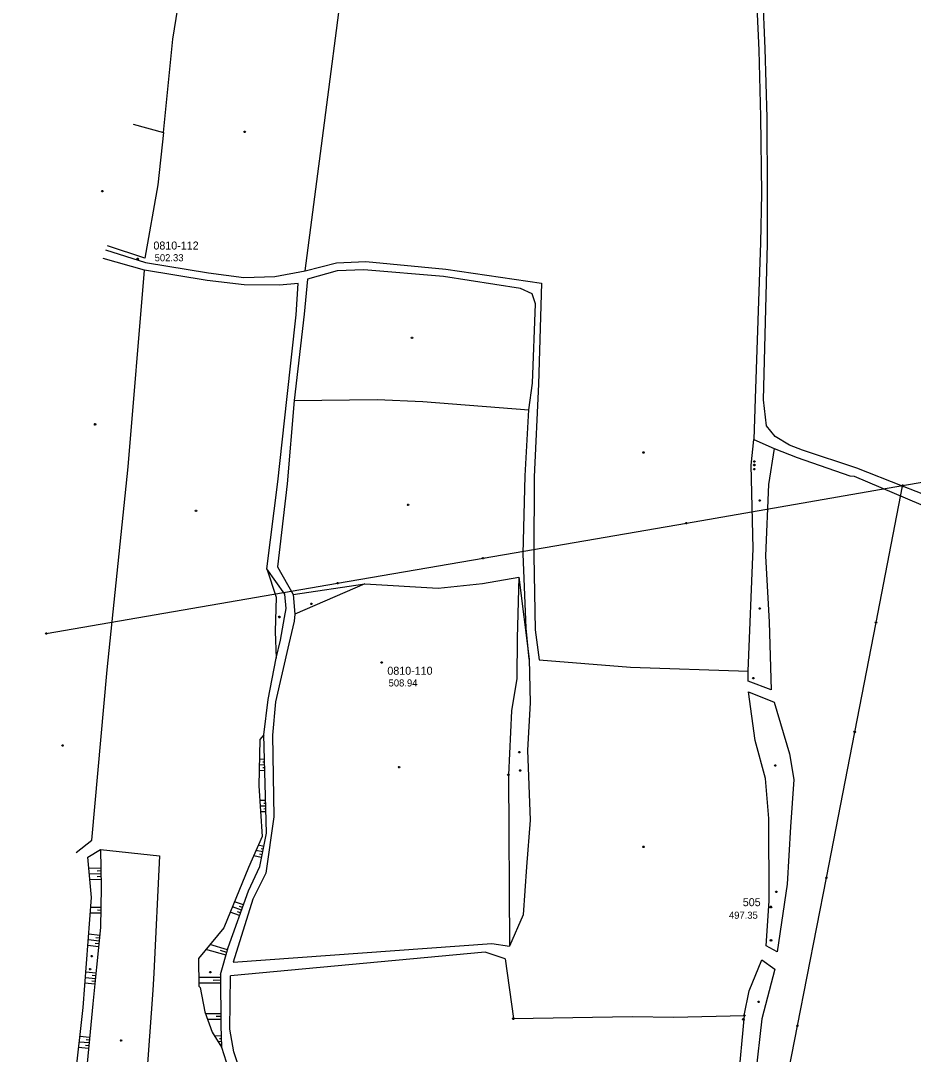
# Model space of a CAD drawing. Extents: x -664960 to -662754, y -993849 to -991145.
# Drawn here: x -664861.7 to -664482.4, y -993104.4 to -992665.4 of the extents above; entities that cross this region are included whole.
import ezdxf

# ---------------------------------------------------------------- set-up
doc = ezdxf.new("R2010")
doc.units = 0
for name, color, linetype in [('Vrstva 1', 7, 'Continuous'), ('Vrstva 12', 7, 'Continuous'), ('Vrstva 13', 7, 'Continuous'), ('Vrstva 18', 7, 'Continuous'), ('Vrstva 27', 7, 'Continuous'), ('Vrstva 29', 7, 'Continuous'), ('Vrstva 37', 7, 'Continuous'), ('Vrstva 57', 7, 'Continuous'), ('Vrstva 63', 7, 'Continuous'), ('Vrstva 8', 7, 'Continuous')]:
    doc.layers.add(name, color=color, linetype=linetype)

msp = doc.modelspace()

# ---------------------------------------------------------------- linework, layer by layer
at = {"layer": 'Vrstva 12'}
msp.add_lwpolyline([(-664813.951, -992709.374), (-664800.96, -992712.82), (-664803.48, -992735.03), (-664809.02, -992766.19), (-664824.81, -992761.06)], dxfattribs=at)
at = {"layer": 'Vrstva 13'}
for points in [[(-664766.347, -992712.286), (-664766.167, -992712.586), (-664766.347, -992712.886), (-664766.707, -992712.886), (-664766.887, -992712.586), (-664766.707, -992712.286), (-664766.347, -992712.286)], [(-664826.854, -992737.453), (-664826.674, -992737.753), (-664826.854, -992738.053), (-664827.214, -992738.053), (-664827.394, -992737.753), (-664827.214, -992737.453), (-664826.854, -992737.453)], [(-664695.26, -992799.766), (-664695.08, -992800.066), (-664695.26, -992800.366), (-664695.62, -992800.366), (-664695.8, -992800.066), (-664695.62, -992799.766), (-664695.26, -992799.766)], [(-664829.885, -992836.502), (-664829.705, -992836.802), (-664829.885, -992837.102), (-664830.245, -992837.102), (-664830.425, -992836.802), (-664830.245, -992836.502), (-664829.885, -992836.502)], [(-664596.895, -992848.458), (-664596.715, -992848.758), (-664596.895, -992849.058), (-664597.255, -992849.058), (-664597.435, -992848.758), (-664597.255, -992848.458), (-664596.895, -992848.458)], [(-664696.913, -992870.741), (-664696.733, -992871.041), (-664696.913, -992871.341), (-664697.273, -992871.341), (-664697.453, -992871.041), (-664697.273, -992870.741), (-664696.913, -992870.741)], [(-664547.497, -992868.823), (-664547.317, -992869.123), (-664547.497, -992869.423), (-664547.857, -992869.423), (-664548.037, -992869.123), (-664547.857, -992868.823), (-664547.497, -992868.823)], [(-664787.011, -992873.217), (-664786.831, -992873.517), (-664787.011, -992873.817), (-664787.371, -992873.817), (-664787.551, -992873.517), (-664787.371, -992873.217), (-664787.011, -992873.217)], [(-664737.988, -992912.78), (-664737.808, -992913.08), (-664737.988, -992913.38), (-664738.348, -992913.38), (-664738.528, -992913.08), (-664738.348, -992912.78), (-664737.988, -992912.78)], [(-664547.497, -992914.751), (-664547.317, -992915.051), (-664547.497, -992915.351), (-664547.857, -992915.351), (-664548.037, -992915.051), (-664547.857, -992914.751), (-664547.497, -992914.751)], [(-664751.581, -992918.346), (-664751.401, -992918.646), (-664751.581, -992918.946), (-664751.941, -992918.946), (-664752.121, -992918.646), (-664751.941, -992918.346), (-664751.581, -992918.346)], [(-664843.741, -992972.897), (-664843.561, -992973.197), (-664843.741, -992973.497), (-664844.101, -992973.497), (-664844.281, -992973.197), (-664844.101, -992972.897), (-664843.741, -992972.897)], [(-664649.659, -992975.744), (-664649.479, -992976.044), (-664649.659, -992976.344), (-664650.019, -992976.344), (-664650.199, -992976.044), (-664650.019, -992975.744), (-664649.659, -992975.744)], [(-664700.722, -992982.14), (-664700.542, -992982.44), (-664700.722, -992982.74), (-664701.082, -992982.74), (-664701.262, -992982.44), (-664701.082, -992982.14), (-664700.722, -992982.14)], [(-664540.942, -992981.379), (-664540.762, -992981.679), (-664540.942, -992981.979), (-664541.302, -992981.979), (-664541.482, -992981.679), (-664541.302, -992981.379), (-664540.942, -992981.379)], [(-664649.298, -992983.518), (-664649.118, -992983.818), (-664649.298, -992984.118), (-664649.658, -992984.118), (-664649.838, -992983.818), (-664649.658, -992983.518), (-664649.298, -992983.518)], [(-664596.895, -993015.992), (-664596.715, -993016.292), (-664596.895, -993016.592), (-664597.255, -993016.592), (-664597.435, -993016.292), (-664597.255, -993015.992), (-664596.895, -993015.992)], [(-664540.424, -993035.07), (-664540.244, -993035.37), (-664540.424, -993035.67), (-664540.784, -993035.67), (-664540.964, -993035.37), (-664540.784, -993035.07), (-664540.424, -993035.07)], [(-664831.3, -993062.334), (-664831.12, -993062.634), (-664831.3, -993062.934), (-664831.66, -993062.934), (-664831.84, -993062.634), (-664831.66, -993062.334), (-664831.3, -993062.334)], [(-664832.016, -993067.929), (-664831.836, -993068.229), (-664832.016, -993068.529), (-664832.376, -993068.529), (-664832.556, -993068.229), (-664832.376, -993067.929), (-664832.016, -993067.929)], [(-664780.956, -993069.225), (-664780.776, -993069.525), (-664780.956, -993069.825), (-664781.316, -993069.825), (-664781.496, -993069.525), (-664781.316, -993069.225), (-664780.956, -993069.225)], [(-664548.014, -993081.807), (-664547.834, -993082.107), (-664548.014, -993082.407), (-664548.374, -993082.407), (-664548.554, -993082.107), (-664548.374, -993081.807), (-664548.014, -993081.807)], [(-664818.837, -993098.191), (-664818.657, -993098.491), (-664818.837, -993098.791), (-664819.197, -993098.791), (-664819.377, -993098.491), (-664819.197, -993098.191), (-664818.837, -993098.191)]]:
    msp.add_lwpolyline(points, dxfattribs=at)
at = {"layer": 'Vrstva 18'}
for points in [[(-664654.29, -992985.33), (-664654.11, -992985.63), (-664654.29, -992985.93), (-664654.65, -992985.93), (-664654.83, -992985.63), (-664654.65, -992985.33), (-664654.29, -992985.33)], [(-664554.07, -993087.64), (-664553.89, -993087.94), (-664554.07, -993088.24), (-664554.43, -993088.24), (-664554.61, -993087.94), (-664554.43, -993087.64), (-664554.07, -993087.64)], [(-664652.17, -993088.92), (-664651.99, -993089.22), (-664652.17, -993089.52), (-664652.53, -993089.52), (-664652.71, -993089.22), (-664652.53, -993088.92), (-664652.17, -993088.92)]]:
    msp.add_lwpolyline(points, dxfattribs=at)
at = {"layer": 'Vrstva 27'}
for points in [[(-664549.26, -992653.21), (-664548.03, -992677.85), (-664547.4, -992706.27), (-664546.88, -992738.77), (-664547.41, -992759.68), (-664549.63, -992825.84), (-664550.21, -992843.18), (-664541.56, -992847.02), (-664531.738, -992850.961), (-664509.431, -992858.668), (-664507.541, -992858.79), (-664467.903, -992875.621), (-664436.08, -992888.029), (-664408.092, -992896.554), (-664386.885, -992895.077), (-664374.052, -992898.604), (-664348.318, -992906.034), (-664324.204, -992913.897), (-664309.56, -992921.692), (-664284.985, -992937.084), (-664263.986, -992955.329), (-664251.663, -992973.809), (-664241.683, -992988.903), (-664240.873, -992991.914)], [(-664463.793, -992872.084), (-664487.02, -992863.072), (-664506.398, -992855.488), (-664529.544, -992847.783), (-664535, -992845.62), (-664541.14, -992842.02), (-664544.77, -992837.4), (-664546.1, -992826.44), (-664544.46, -992760.18), (-664544.35, -992738.4), (-664544.54, -992706.6), (-664545.38, -992677.24), (-664546.38, -992653.52)], [(-664825.73, -992762.66), (-664808.65, -992768.08), (-664781.85, -992772.4), (-664766.92, -992774.42), (-664753.75, -992773.95), (-664740.88, -992771.61), (-664727.55, -992768.23), (-664715.01, -992767.59), (-664681.1, -992770.9), (-664640.46, -992776.78), (-664641.66, -992819.75), (-664643.57, -992859.11), (-664643.74, -992892.6), (-664643.11, -992924.06), (-664641.42, -992936.82)], [(-664776.82, -993070.5), (-664773.54, -993059.03), (-664764.9, -993034.95), (-664760.12, -993024.65), (-664757.31, -993010.47), (-664758.33, -992968.66), (-664756.58, -992953.66), (-664753.09, -992936.06), (-664751.24, -992928.44), (-664749.63, -992918.9), (-664748.95, -992914.99), (-664749.52, -992909), (-664757.07, -992898.13), (-664752.39, -992861.25), (-664748.63, -992826.29), (-664744.62, -992790.3), (-664743.77, -992777.04), (-664751.77, -992777.72), (-664766.79, -992777.55), (-664782.49, -992775.73), (-664809.14, -992771.38), (-664826.69, -992766.35)], [(-664645.72, -992936.59), (-664646.98, -992923.41), (-664648.14, -992891.87), (-664647.42, -992858.62), (-664645.74, -992830.7), (-664644.28, -992819.27), (-664643.03, -992785.66), (-664644.35, -992781.31), (-664649.31, -992779.12), (-664682.11, -992773.97), (-664715.92, -992771.21), (-664727.27, -992771.63), (-664739.9, -992775.12), (-664741.19, -992790.04), (-664745.55, -992826.68), (-664748.49, -992862.04), (-664752.56, -992897.35), (-664745.96, -992909.01), (-664745.22, -992917.44), (-664745.54, -992920.45), (-664747.76, -992930.07), (-664753.45, -992954.63), (-664754.76, -992968.76), (-664754.08, -993003.44), (-664757.51, -993027.48), (-664763.09, -993038.52), (-664771.44, -993065.28), (-664661.57, -993057.32), (-664653.95, -993058.39)], [(-664655.82, -993063.79), (-664664.37, -993061.05), (-664772.56, -993071.1)], [(-664776.82, -993070.5), (-664776.67, -993092.1), (-664776.38, -993101.37), (-664771.43, -993116.89)], [(-664758.94, -993139.61), (-664771.07, -993103.34), (-664772.77, -993093.75), (-664772.56, -993071.1)]]:
    msp.add_lwpolyline(points, dxfattribs=at)
at = {"layer": 'Vrstva 29'}
msp.add_lwpolyline([(-664549.8, -992853.79), (-664549.62, -992854.09), (-664549.8, -992854.39), (-664550.16, -992854.39), (-664550.34, -992854.09), (-664550.16, -992853.79), (-664549.8, -992853.79)], dxfattribs=at)
at = {"layer": 'Vrstva 37'}
for points in [[(-664486.84, -992862.772), (-664486.66, -992863.072), (-664486.84, -992863.372), (-664487.2, -992863.372), (-664487.38, -992863.072), (-664487.2, -992862.772), (-664486.84, -992862.772)], [(-664486.795, -992862.482), (-664486.615, -992862.782), (-664486.795, -992863.082), (-664487.155, -992863.082), (-664487.335, -992862.782), (-664487.155, -992862.482), (-664486.795, -992862.482)], [(-664578.69, -992878.53), (-664578.51, -992878.83), (-664578.69, -992879.13), (-664579.05, -992879.13), (-664579.23, -992878.83), (-664579.05, -992878.53), (-664578.69, -992878.53)], [(-664665.09, -992893.36), (-664664.91, -992893.66), (-664665.09, -992893.96), (-664665.45, -992893.96), (-664665.63, -992893.66), (-664665.45, -992893.36), (-664665.09, -992893.36)], [(-664726.89, -992903.97), (-664726.71, -992904.27), (-664726.89, -992904.57), (-664727.25, -992904.57), (-664727.43, -992904.27), (-664727.25, -992903.97), (-664726.89, -992903.97)], [(-664498.111, -992920.62), (-664497.931, -992920.92), (-664498.111, -992921.22), (-664498.471, -992921.22), (-664498.651, -992920.92), (-664498.471, -992920.62), (-664498.111, -992920.62)], [(-664850.67, -992925.29), (-664850.49, -992925.59), (-664850.67, -992925.89), (-664851.03, -992925.89), (-664851.21, -992925.59), (-664851.03, -992925.29), (-664850.67, -992925.29)], [(-664507.134, -992967.179), (-664506.954, -992967.479), (-664507.134, -992967.779), (-664507.494, -992967.779), (-664507.674, -992967.479), (-664507.494, -992967.179), (-664507.134, -992967.179)], [(-664519.153, -993029.127), (-664518.973, -993029.427), (-664519.153, -993029.727), (-664519.513, -993029.727), (-664519.693, -993029.427), (-664519.513, -993029.127), (-664519.153, -993029.127)], [(-664531.485, -993092.029), (-664531.305, -993092.329), (-664531.485, -993092.629), (-664531.845, -993092.629), (-664532.025, -993092.329), (-664531.845, -993092.029), (-664531.485, -993092.029)]]:
    msp.add_lwpolyline(points, dxfattribs=at)
at = {"layer": 'Vrstva 57'}
for points in [[(-664850.85, -992925.59), (-664727.07, -992904.27), (-664665.27, -992893.66), (-664578.87, -992878.83), (-664486.975, -992862.782), (-664378.158, -992844.317), (-664294.99, -992830.081), (-664180.69, -992810.49)], [(-664522.999, -993424.664), (-664549.676, -993372.01), (-664575.68, -993321.894), (-664564.945, -993264.353), (-664554.433, -993209.057), (-664543.48, -993153.084), (-664531.665, -993092.329), (-664519.333, -993029.427), (-664507.314, -992967.479), (-664498.291, -992920.92), (-664487.02, -992863.072)]]:
    msp.add_lwpolyline(points, dxfattribs=at)
at = {"layer": 'Vrstva 63'}
for p, q in [((-664758.017, -992981.483), (-664760.287, -992981.538)), ((-664758.076, -992979.083), (-664760.237, -992979.136)), ((-664758.046, -992980.283), (-664758.784, -992980.301)), ((-664757.959, -992983.882), (-664760.337, -992983.94)), ((-664757.988, -992982.682), (-664758.762, -992982.701)), ((-664757.649, -992996.579), (-664760.081, -992996.638)), ((-664757.59, -992998.978), (-664759.933, -992999.035)), ((-664757.62, -992997.778), (-664758.415, -992997.798)), ((-664757.532, -993001.377), (-664759.785, -993001.432)), ((-664757.561, -993000.178), (-664758.326, -993000.196)), ((-664758.418, -993016.06), (-664760.762, -993015.596)), ((-664758.651, -993017.237), (-664759.519, -993017.065)), ((-664759.351, -993020.769), (-664762.738, -993020.097)), ((-664758.884, -993018.414), (-664761.75, -993017.846)), ((-664759.118, -993019.592), (-664760.159, -993019.385)), ((-664827.647, -993025.305), (-664832.677, -993025.41)), ((-664827.597, -993027.705), (-664832.459, -993027.806)), ((-664827.547, -993030.104), (-664832.24, -993030.202)), ((-664827.622, -993026.505), (-664829.269, -993026.539)), ((-664827.572, -993028.904), (-664829.163, -993028.938)), ((-664827.627, -993042.045), (-664831.878, -993041.973)), ((-664827.647, -993043.244), (-664829.087, -993043.22)), ((-664767.856, -993043.188), (-664771.737, -993041.796)), ((-664767.045, -993040.929), (-664770.83, -993039.571)), ((-664768.261, -993044.318), (-664769.57, -993043.849)), ((-664767.451, -993042.059), (-664768.727, -993041.601)), ((-664827.667, -993044.444), (-664832.064, -993044.37)), ((-664768.667, -993045.447), (-664772.643, -993044.021)), ((-664828.359, -993056.272), (-664832.954, -993055.8)), ((-664828.114, -993053.885), (-664832.768, -993053.407)), ((-664828.236, -993055.079), (-664829.776, -993054.921)), ((-664828.604, -993058.66), (-664833.14, -993058.194)), ((-664828.482, -993057.466), (-664830.002, -993057.31)), ((-664774.459, -993062.244), (-664782.969, -993059.81)), ((-664773.799, -993059.936), (-664781.295, -993057.793)), ((-664774.129, -993061.09), (-664776.794, -993060.328)), ((-664829.744, -993069.856), (-664834.015, -993069.435)), ((-664830.216, -993074.633), (-664834.387, -993074.222)), ((-664829.98, -993072.245), (-664834.201, -993071.828)), ((-664830.098, -993073.439), (-664831.495, -993073.301)), ((-664829.862, -993071.051), (-664831.276, -993070.911)), ((-664776.811, -993071.743), (-664786.062, -993071.807)), ((-664776.795, -993074.143), (-664786.015, -993074.207)), ((-664776.803, -993072.943), (-664779.878, -993072.964)), ((-664776.704, -993087.162), (-664783.12, -993087.206)), ((-664776.688, -993089.562), (-664782.269, -993089.6)), ((-664776.696, -993088.362), (-664778.693, -993088.376)), ((-664776.53, -993096.572), (-664779.303, -993096.659)), ((-664832.624, -993099.562), (-664836.818, -993099.161)), ((-664832.396, -993097.172), (-664836.553, -993096.775)), ((-664832.738, -993100.756), (-664834.141, -993100.622)), ((-664832.51, -993098.367), (-664833.9, -993098.234)), ((-664776.455, -993098.971), (-664777.842, -993099.015)), ((-664776.493, -993097.772), (-664777.185, -993097.793)), ((-664776.418, -993100.171), (-664776.648, -993100.178)), ((-664832.852, -993101.951), (-664837.084, -993101.546)), ((-664776.38, -993101.37), (-664776.38, -993101.37))]:
    msp.add_line(p, q, dxfattribs=at)
for points in [[(-664800.96, -992712.82), (-664797.02, -992673.16), (-664790.26, -992630.94), (-664785.81, -992582.58), (-664786.07, -992548.06), (-664785.94, -992543.77), (-664786.47, -992521.58), (-664789.59, -992497.46), (-664794, -992477.1), (-664797.68, -992463.73), (-664797.77, -992460.54), (-664807.2, -992434.68), (-664814.81, -992413.16), (-664819.55, -992398.64), (-664824.21, -992400.64)], [(-664740.88, -992771.61), (-664732.98, -992711.95), (-664724.72, -992647.59), (-664721.69, -992617.04), (-664718.92, -992552.98), (-664719.06, -992531.76), (-664721.04, -992495.55), (-664723.27, -992472.75), (-664729.45, -992426.22)], [(-664838.06, -993018.65), (-664831.53, -993013.42), (-664824.97, -992941.06), (-664816.06, -992854.88), (-664809.14, -992771.38)], [(-664745.55, -992826.68), (-664710.21, -992826.3), (-664690.81, -992827.09), (-664645.74, -992830.7)], [(-664542.77, -992949.6), (-664552.54, -992945.82), (-664552.67, -992941.65), (-664550.47, -992889.58), (-664551.29, -992854.12), (-664550.21, -992843.18)], [(-664541.56, -992847.02), (-664543.99, -992862.33), (-664545.23, -992892.67), (-664543.68, -992920.85), (-664542.77, -992949.6)], [(-664549.77, -992852.24), (-664549.59, -992852.54), (-664549.77, -992852.84), (-664550.13, -992852.84), (-664550.31, -992852.54), (-664550.13, -992852.24), (-664549.77, -992852.24)], [(-664549.85, -992855.58), (-664549.67, -992855.88), (-664549.85, -992856.18), (-664550.21, -992856.18), (-664550.39, -992855.88), (-664550.21, -992855.58), (-664549.85, -992855.58)], [(-664757.07, -992898.13), (-664753.11, -992910.21), (-664753.63, -992924.8), (-664753.09, -992936.06)], [(-664715.42, -992904.6), (-664684.31, -992906.39), (-664665.51, -992904.45), (-664650.04, -992901.74), (-664650.82, -992927.69), (-664650.85, -992944.79), (-664653.1, -992958.51), (-664654.47, -992985.63), (-664653.95, -993058.39)], [(-664650.04, -992901.74), (-664645.72, -992936.59), (-664645.21, -992955.05), (-664646.38, -992975.26), (-664645.28, -993004.89), (-664646.79, -993024.78), (-664648.2, -993045.12), (-664653.95, -993058.39)], [(-664745.96, -992909.01), (-664715.42, -992904.6), (-664745.22, -992917.44)], [(-664641.42, -992936.82), (-664602.54, -992939.99), (-664552.67, -992941.65)], [(-664550.23, -992944.29), (-664550.05, -992944.59), (-664550.23, -992944.89), (-664550.59, -992944.89), (-664550.77, -992944.59), (-664550.59, -992944.29), (-664550.23, -992944.29)], [(-664540.28, -993060.91), (-664544.96, -993058.26), (-664543.66, -993039.18), (-664543.76, -993004.16), (-664545.22, -992987.28), (-664549.58, -992971.06), (-664552.52, -992950.44), (-664541.49, -992954.8), (-664535.002, -992976.758), (-664533.139, -992987.638), (-664534.675, -993007.788), (-664536.025, -993032.07), (-664540.28, -993060.91)], [(-664758.33, -992968.66), (-664760.06, -992970.67), (-664760.47, -992990.32), (-664759.14, -993011.9), (-664764.93, -993025.09), (-664775.32, -993050.59), (-664786.22, -993063.73), (-664785.99, -993075.48), (-664785.5, -993076), (-664783.41, -993086.39), (-664780.37, -993094.94), (-664776.38, -993101.37)], [(-664831.55, -993037.76), (-664833.11, -993020.67), (-664827.81, -993017.45), (-664827.48, -993033.32), (-664827.77, -993050.54), (-664829.5, -993067.38), (-664831.04, -993082.99), (-664834.29, -993116.99), (-664836.8, -993137.97), (-664836.67, -993153.36), (-664835.64, -993165.38), (-664834.4, -993175.41), (-664846.97, -993182.62), (-664855.3, -993197.64), (-664859.62, -993209.7), (-664861.71, -993206.41), (-664858.51, -993197.12), (-664853.19, -993181.68), (-664846.56, -993165.7), (-664843.22, -993150.84), (-664841.14, -993136.53), (-664838.57, -993114.89), (-664835.19, -993084.54), (-664831.55, -993037.76)], [(-664827.81, -993017.45), (-664802.73, -993020.1), (-664805.16, -993069.86), (-664805.5, -993077.19), (-664811.42, -993157.27), (-664833.14, -993178.18), (-664834.4, -993175.41)], [(-664542.76, -993055.65), (-664542.58, -993055.95), (-664542.76, -993056.25), (-664543.12, -993056.25), (-664543.3, -993055.95), (-664543.12, -993055.65), (-664542.76, -993055.65)], [(-664655.82, -993063.79), (-664652.35, -993089.22), (-664601.96, -993088.33), (-664584.23, -993088.63), (-664554.25, -993087.94)], [(-664554.25, -993087.94), (-664552.21, -993077.47), (-664546.85, -993064.24), (-664541.29, -993068.2)], [(-664541.29, -993068.2), (-664546.848, -993089.32), (-664549.459, -993113.136), (-664550.45, -993153.095), (-664548.592, -993189.058), (-664550.275, -993205.084), (-664554.048, -993218.194), (-664563.831, -993237.797), (-664570.304, -993250.681), (-664566.308, -993263.028), (-664575.608, -993269.908), (-664575.58, -993270.94), (-664583.879, -993275.133)], [(-664554.25, -993087.94), (-664556.941, -993116.782), (-664555.472, -993152.376), (-664555.433, -993166.316), (-664555.866, -993180.523), (-664562.815, -993208.847), (-664567.677, -993230.44), (-664570.498, -993241.142), (-664581.807, -993246.578), (-664586.352, -993248.126), (-664607.195, -993246.026), (-664651.264, -993240.564), (-664666.443, -993238.925), (-664677.101, -993237.259), (-664696.743, -993250.798), (-664713.926, -993249.625), (-664732.687, -993253.923), (-664743.665, -993255.481), (-664754.532, -993256.093), (-664772.207, -993254.41)], [(-664554.51, -993089.21), (-664554.33, -993089.51), (-664554.51, -993089.81), (-664554.87, -993089.81), (-664555.05, -993089.51), (-664554.87, -993089.21), (-664554.51, -993089.21)]]:
    msp.add_lwpolyline(points, dxfattribs=at)
at = {"layer": 'Vrstva 8'}
for points in [[(-664811.82, -992766.27), (-664811.64, -992766.57), (-664811.82, -992766.87), (-664812.18, -992766.87), (-664812.36, -992766.57), (-664812.18, -992766.27), (-664811.82, -992766.27)], [(-664708.13, -992937.66), (-664707.95, -992937.96), (-664708.13, -992938.26), (-664708.49, -992938.26), (-664708.67, -992937.96), (-664708.49, -992937.66), (-664708.13, -992937.66)], [(-664542.8, -993041.49), (-664542.62, -993041.79), (-664542.8, -993042.09), (-664543.16, -993042.09), (-664543.34, -993041.79), (-664543.16, -993041.49), (-664542.8, -993041.49)]]:
    msp.add_lwpolyline(points, dxfattribs=at)

# ---------------------------------------------------------------- texts
at = {"layer": 'Vrstva 1'}
for s, p in [('0810-112', (-664805.306, -992762.562)), ('0810-110', (-664705.91, -992943.16)), ('505', (-664554.893, -993041.458))]:
    msp.add_text(s, height=3.4, dxfattribs=at).set_placement(p)
at = {"layer": 'Vrstva 63'}
for s, p in [('502.33', (-664804.783, -992767.542)), ('508.94', (-664705.386, -992948.14)), ('497.35', (-664560.78, -993046.798))]:
    msp.add_text(s, height=3, dxfattribs=at).set_placement(p)

doc.saveas('drawing.dxf')
